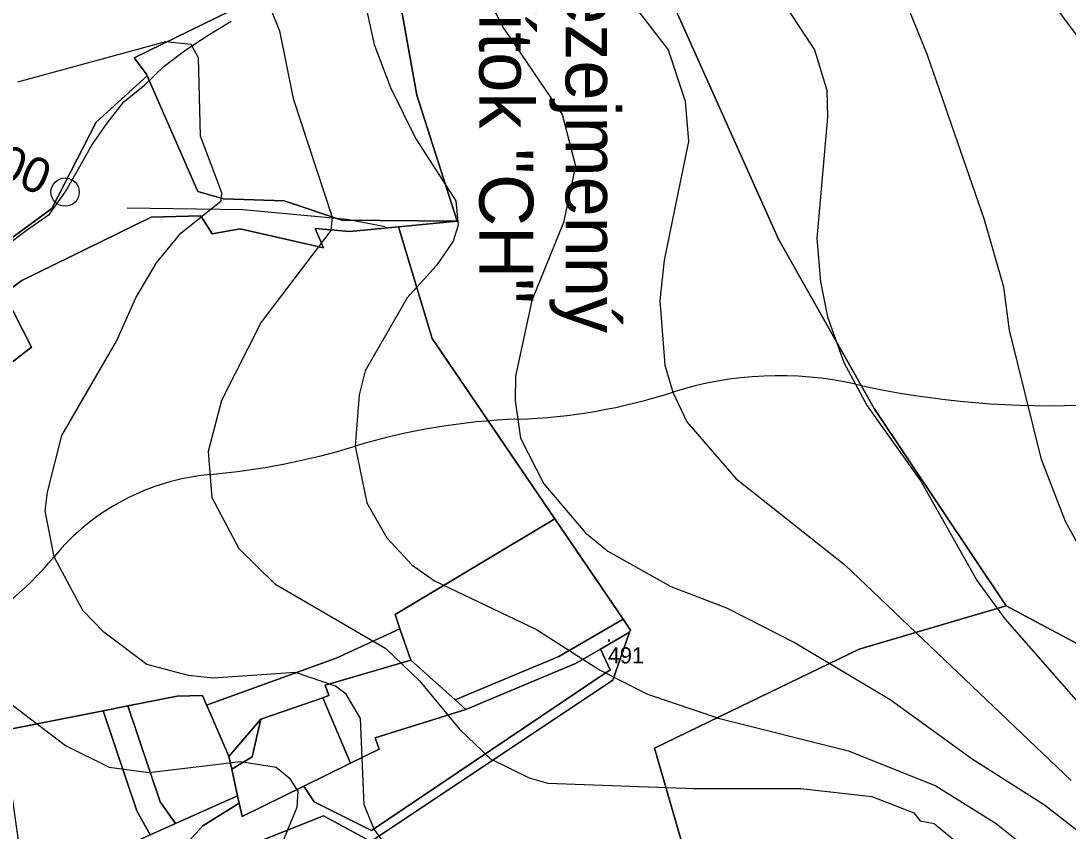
# Model space of a CAD drawing. Extents: x -510989 to -501240, y -1184665 to -1176089.
# Drawn here: x -509708.8 to -509320.3, y -1177679.8 to -1177379.3 of the extents above; entities that cross this region are included whole.
import ezdxf

# ---------------------------------------------------------------- set-up
doc = ezdxf.new("R2010")
doc.units = 0
for name, color, linetype in [('lesni_pozemek', 7, 'Continuous'), ('NAVRH_rozvodnice', 7, 'Continuous'), ('orna_puda', 7, 'Continuous'), ('ostatni_plocha_x_neplodna_puda', 7, 'Continuous'), ('ostatni_plocha_x_ostatni_komunikace', 7, 'Continuous'), ('STAV_vyrazne_udolnice', 7, 'Continuous'), ('trasovani_toku', 7, 'Continuous'), ('trvaly_travni_porost', 7, 'Continuous'), ('vrstevnice_01', 7, 'Continuous'), ('vrstevnice_02', 7, 'Continuous'), ('vrstevnice_05', 7, 'Continuous'), ('zahrada', 7, 'Continuous'), ('zastavena_plocha_a_nadvori', 7, 'Continuous')]:
    doc.layers.add(name, color=color, linetype=linetype)

msp = doc.modelspace()

# ---------------------------------------------------------------- linework, layer by layer
at = {"layer": 'lesni_pozemek'}
for points in [[(-509307.58, -1177615.25), (-509343.27, -1177596.17), (-509392.19, -1177523.08), (-509427.76, -1177460.22), (-509483.45, -1177336)], [(-509483.45, -1177336), (-509427.76, -1177460.22), (-509392.19, -1177523.08), (-509343.27, -1177596.17), (-509397.8, -1177612.27), (-509449.55, -1177637.32), (-509473.73, -1177649.02), (-509463.07, -1177685.78)], [(-509668.22, -1177702.68), (-509596.6, -1177674.14), (-509578.99, -1177683.68), (-509489.24, -1177623.79), (-509482.96, -1177605.95), (-509482.69, -1177605.19), (-509485.42, -1177601.19), (-509510.77, -1177563.96), (-509556.29, -1177497.11), (-509568.76, -1177455.65), (-509546.91, -1177453.53), (-509561.97, -1177406.86), (-509572.95, -1177345.3)], [(-509631, -1177375.54), (-509666.85, -1177393), (-509662.19, -1177399.04), (-509661.92, -1177399.66), (-509680.94, -1177416.84), (-509697.38, -1177448.86), (-509762.27, -1177496.39), (-509774.65, -1177504.38), (-509790.33, -1177514.5), (-509803.69, -1177521.05), (-509822.77, -1177518.7), (-509793.37, -1177502.17), (-509802.43, -1177486.07), (-509850.77, -1177515.75), (-509864.33, -1177527.68), (-509871.08, -1177519.58), (-509909.37, -1177546.26), (-509910.59, -1177544.53), (-509920.45, -1177530.57), (-509905.31, -1177521.45), (-509903.04, -1177450.59), (-509835.36, -1177418.23), (-509751.69, -1177352.23)]]:
    msp.add_lwpolyline(points, dxfattribs=at)
msp.add_lwpolyline([(-509397.8, -1177612.27), (-509343.27, -1177596.17), (-509307.58, -1177615.25), (-509273.09, -1177665), (-509315.44, -1177685.24), (-509336.68, -1177703.21), (-509377.83, -1177696.33), (-509381.06, -1177712.35), (-509395.4, -1177703.59), (-509428.68, -1177701.8), (-509460.46, -1177711.83), (-509462.62, -1177705), (-509463.07, -1177685.78), (-509473.73, -1177649.02), (-509449.55, -1177637.32)], close=True, dxfattribs=at)
at = {"layer": 'NAVRH_rozvodnice'}
for centre, radius, start, end in [((-509327.54, -1177195.98), 325.99, 257.3092, 319.4646), ((-509427.52, -1177639.96), 129.11, 77.3092, 107.7616), ((-509531.7, -1177314.74), 212.38, 271.9542, 287.7616), ((-509516.41, -1177762.7), 235.84, 91.9542, 106.8599), ((-509663.19, -1177278.37), 270.25, 275.2094, 286.8599), ((-509630.93, -1177632.26), 85.11, 95.2094, 140.3942), ((-509791.78, -1177499.16), 123.67, 297.3565, 320.3942)]:
    msp.add_arc(centre, radius, start, end, dxfattribs=at)
at = {"layer": 'orna_puda'}
for points in [[(-509570.02, -1177599.49), (-509510.77, -1177563.96), (-509485.42, -1177601.19), (-509509.18, -1177614.97), (-509547.74, -1177631.1), (-509564.19, -1177616.36), (-509568.18, -1177604.8)], [(-509719.86, -1177643.27), (-509678.3, -1177635.13), (-509665.79, -1177672.22), (-509660.81, -1177681.17), (-509707.03, -1177702.63), (-509708.88, -1177689.34), (-509711.8, -1177668.29), (-509713.07, -1177664.37)]]:
    msp.add_lwpolyline(points, close=True, dxfattribs=at)
at = {"layer": 'ostatni_plocha_x_neplodna_puda'}
for points in [[(-509493.75, -1177612.24), (-509482.96, -1177605.95), (-509489.24, -1177623.79), (-509578.99, -1177683.68), (-509596.6, -1177674.14), (-509668.22, -1177702.68), (-509677.09, -1177705.72), (-509669.63, -1177698.49), (-509651.95, -1177689.42), (-509641.31, -1177677.76), (-509627.8, -1177669.37), (-509626.7, -1177674.34), (-509603.8, -1177663.1), (-509599.97, -1177668.97), (-509578.73, -1177679.51), (-509490.25, -1177619.92)], [(-509631.64, -1177652.13), (-509619.84, -1177638.21), (-509623.01, -1177652.18), (-509630.61, -1177656.76)]]:
    msp.add_lwpolyline(points, close=True, dxfattribs=at)
at = {"layer": 'ostatni_plocha_x_ostatni_komunikace'}
for points in [[(-509482.69, -1177605.19), (-509482.96, -1177605.95), (-509493.75, -1177612.24), (-509503.04, -1177617.66), (-509543.7, -1177634.72), (-509547.74, -1177631.1), (-509509.18, -1177614.97), (-509485.42, -1177601.19)], [(-509628.4, -1177666.69), (-509627.8, -1177669.37), (-509641.31, -1177677.76), (-509651.95, -1177689.42), (-509669.63, -1177698.49), (-509677.09, -1177705.72), (-509678.31, -1177706.14), (-509689.95, -1177715.27), (-509704.37, -1177721.75), (-509707.03, -1177702.63), (-509660.81, -1177681.17), (-509651.5, -1177677.01)]]:
    msp.add_lwpolyline(points, close=True, dxfattribs=at)
at = {"layer": 'STAV_vyrazne_udolnice'}
msp.add_lwpolyline([(-509669.37, -1177448.54), (-509626.47, -1177449.24), (-509587.78, -1177452.75), (-509573.72, -1177455.57)], dxfattribs=at)
at = {"layer": 'trasovani_toku'}
for p, q in [((-509639.3, -1177384.58), (-509630.8, -1177379.32)), ((-509647.68, -1177390.04), (-509639.3, -1177384.58)), ((-509655.63, -1177396.11), (-509647.68, -1177390.04)), ((-509662.86, -1177403.02), (-509655.63, -1177396.11)), ((-509670.67, -1177409.27), (-509662.86, -1177403.02)), ((-509676.83, -1177417.14), (-509670.67, -1177409.27)), ((-509682.46, -1177425.41), (-509676.83, -1177417.14)), ((-509687.42, -1177434.09), (-509682.46, -1177425.41)), ((-509692.41, -1177442.76), (-509687.42, -1177434.09)), ((-509698.15, -1177450.94), (-509692.41, -1177442.76)), ((-509706.4, -1177456.59), (-509698.15, -1177450.94)), ((-509714.35, -1177462.66), (-509706.4, -1177456.59))]:
    msp.add_line(p, q, dxfattribs=at)
msp.add_circle((-509692.41, -1177442.76), 5.25, dxfattribs=at)
at = {"layer": 'trvaly_travni_porost'}
for points in [[(-509572.95, -1177345.3), (-509561.97, -1177406.86), (-509546.91, -1177453.53), (-509589.76, -1177453.23), (-509611.17, -1177445.97), (-509633.68, -1177445.21), (-509643.12, -1177442.55), (-509661.92, -1177399.66), (-509662.19, -1177399.04), (-509666.85, -1177393), (-509631, -1177375.54), (-509588.68, -1177354.29)], [(-509661.92, -1177399.66), (-509643.12, -1177442.55), (-509633.68, -1177445.21), (-509611.17, -1177445.97), (-509589.76, -1177453.23), (-509546.91, -1177453.53), (-509568.76, -1177455.65), (-509586.79, -1177457.4), (-509599.68, -1177456.28), (-509596.6, -1177463.39), (-509627.43, -1177456.33), (-509637.9, -1177458.29), (-509642.03, -1177451.61), (-509660.52, -1177452), (-509708.48, -1177475.5), (-509715.05, -1177480.43), (-509704.91, -1177500.28), (-509737.25, -1177525.22), (-509754.82, -1177531.88), (-509774.65, -1177504.38), (-509762.27, -1177496.39), (-509697.38, -1177448.86), (-509680.94, -1177416.84)], [(-509568.18, -1177604.8), (-509564.19, -1177616.36), (-509585.32, -1177622.55), (-509595.98, -1177625.67), (-509594.6, -1177629.53), (-509596.8, -1177630.29), (-509619.84, -1177638.21), (-509631.64, -1177652.13), (-509632.2, -1177650.84), (-509639.71, -1177633.49), (-509639.91, -1177633.04), (-509591.84, -1177615.63)], [(-509503.04, -1177617.66), (-509493.75, -1177612.24), (-509490.25, -1177619.92), (-509578.73, -1177679.51), (-509599.97, -1177668.97), (-509603.8, -1177663.1), (-509586.55, -1177654.63), (-509575.89, -1177649.39), (-509577.38, -1177645.15), (-509543.7, -1177634.72)]]:
    msp.add_lwpolyline(points, close=True, dxfattribs=at)
msp.add_lwpolyline([(-509737.25, -1177525.22), (-509704.91, -1177500.28), (-509715.05, -1177480.43), (-509708.48, -1177475.5), (-509660.52, -1177452), (-509642.03, -1177451.61), (-509637.9, -1177458.29), (-509627.43, -1177456.33), (-509596.6, -1177463.39), (-509599.68, -1177456.28), (-509586.79, -1177457.4), (-509568.76, -1177455.65), (-509556.29, -1177497.11), (-509510.77, -1177563.96), (-509570.02, -1177599.49), (-509568.18, -1177604.8), (-509591.84, -1177615.63), (-509639.91, -1177633.04), (-509641.48, -1177629.44), (-509650.79, -1177629.74), (-509669.12, -1177633.33), (-509678.3, -1177635.13), (-509719.86, -1177643.27)], dxfattribs=at)
at = {"layer": 'vrstevnice_01'}
for points in [[(-509584.59, -1177357), (-509577.81, -1177388), (-509571.69, -1177404), (-509562.31, -1177423), (-509547.41, -1177446), (-509546.59, -1177455), (-509548.41, -1177461), (-509554.59, -1177470), (-509565.5, -1177482), (-509581.09, -1177509), (-509583.31, -1177518), (-509584.81, -1177537), (-509580.5, -1177558), (-509573.09, -1177571), (-509563.81, -1177581), (-509555.31, -1177587), (-509517.5, -1177605), (-509494.09, -1177620), (-509476.31, -1177629), (-509449.59, -1177638), (-509401.81, -1177650), (-509369.31, -1177663), (-509347, -1177677), (-509275.91, -1177734)], [(-509492.5, -1177359), (-509468.69, -1177390), (-509462.31, -1177409), (-509461.19, -1177424), (-509470.19, -1177468), (-509471.81, -1177483), (-509469.91, -1177507), (-509466.91, -1177517), (-509461.69, -1177528), (-509443.59, -1177549), (-509403.19, -1177581), (-509319.19, -1177661)], [(-509299.09, -1177605), (-509321.31, -1177565), (-509330.19, -1177542), (-509342.09, -1177494), (-509344.19, -1177478), (-509351.31, -1177453), (-509372.41, -1177392), (-509381.69, -1177369)], [(-509574.19, -1177684), (-509577.81, -1177679), (-509581.5, -1177670), (-509582.81, -1177638), (-509588.19, -1177629), (-509592.09, -1177626), (-509606.91, -1177621), (-509637.5, -1177623), (-509646.59, -1177622), (-509662.09, -1177618), (-509678.09, -1177606), (-509685.81, -1177598), (-509696.5, -1177578), (-509699.81, -1177561), (-509698.91, -1177554), (-509693.69, -1177533), (-509673.31, -1177498), (-509666.19, -1177482), (-509658.5, -1177469), (-509649.5, -1177458), (-509634.5, -1177446), (-509634.31, -1177443), (-509642.19, -1177422), (-509642.91, -1177393), (-509645.69, -1177388), (-509655.19, -1177387), (-509710.09, -1177402)]]:
    msp.add_lwpolyline(points, dxfattribs=at)
at = {"layer": 'vrstevnice_02'}
for points in [[(-509542.81, -1177357), (-509529.81, -1177382), (-509508, -1177414), (-509503, -1177433), (-509507.5, -1177454), (-509519.31, -1177483), (-509525.31, -1177511), (-509525.5, -1177520), (-509523.41, -1177534), (-509514.81, -1177551), (-509499.5, -1177569), (-509491, -1177576), (-509467.69, -1177589), (-509447, -1177597), (-509421.59, -1177610), (-509386.31, -1177631), (-509355.91, -1177653), (-509329.09, -1177670), (-509269.91, -1177716)], [(-509428.81, -1177368), (-509414.41, -1177390), (-509409.81, -1177405), (-509409.5, -1177415), (-509413.5, -1177460), (-509412.19, -1177476), (-509409.5, -1177489), (-509403.5, -1177506), (-509394.81, -1177522), (-509374.91, -1177550), (-509354, -1177587), (-509343.81, -1177601), (-509314, -1177635)], [(-509616.41, -1177374), (-509612.91, -1177383), (-509607.81, -1177408), (-509593.31, -1177452), (-509593.81, -1177457), (-509619.69, -1177491), (-509634.41, -1177520), (-509639.31, -1177539), (-509638, -1177556), (-509628, -1177575), (-509614.59, -1177588), (-509573.41, -1177612), (-509560.91, -1177624), (-509546.09, -1177642), (-509534.59, -1177653), (-509520.19, -1177660), (-509513.31, -1177662), (-509459.09, -1177664), (-509419.41, -1177664), (-509393.09, -1177667), (-509377.59, -1177673), (-509375.19, -1177676), (-509370, -1177677), (-509298.59, -1177736)], [(-509325.81, -1177373), (-509312.41, -1177391)], [(-509720, -1177627), (-509692.31, -1177648), (-509676.09, -1177656), (-509661.41, -1177658), (-509627.31, -1177654), (-509614.09, -1177656), (-509609.31, -1177660), (-509606.09, -1177665), (-509606.41, -1177671), (-509614.69, -1177691)]]:
    msp.add_lwpolyline(points, dxfattribs=at)
at = {"layer": 'zahrada'}
for points in [[(-509619.84, -1177638.21), (-509596.8, -1177630.29), (-509586.55, -1177654.63), (-509603.8, -1177663.1), (-509626.7, -1177674.34), (-509627.8, -1177669.37), (-509628.4, -1177666.69), (-509630.61, -1177656.76), (-509623.01, -1177652.18)], [(-509678.3, -1177635.13), (-509669.12, -1177633.33), (-509657.13, -1177668.92), (-509651.5, -1177677.01), (-509660.81, -1177681.17), (-509665.79, -1177672.22)]]:
    msp.add_lwpolyline(points, close=True, dxfattribs=at)
at = {"layer": 'zastavena_plocha_a_nadvori'}
for points in [[(-509585.32, -1177622.55), (-509564.19, -1177616.36), (-509547.74, -1177631.1), (-509543.7, -1177634.72), (-509577.38, -1177645.15), (-509575.89, -1177649.39), (-509586.55, -1177654.63), (-509596.8, -1177630.29), (-509594.6, -1177629.53), (-509595.98, -1177625.67)], [(-509650.79, -1177629.74), (-509641.48, -1177629.44), (-509639.91, -1177633.04), (-509639.71, -1177633.49), (-509632.2, -1177650.84), (-509631.64, -1177652.13), (-509630.61, -1177656.76), (-509628.4, -1177666.69), (-509651.5, -1177677.01), (-509657.13, -1177668.92), (-509669.12, -1177633.33)]]:
    msp.add_lwpolyline(points, close=True, dxfattribs=at)

# ---------------------------------------------------------------- texts
at = {"layer": 'NAVRH_rozvodnice'}
for s, p in [('Bezejmenný', (-509506.73, -1177347.83)), ('přítok "CH"', (-509538.73, -1177352.24))]:
    msp.add_text(s, height=20, rotation=270, dxfattribs=at).set_placement(p)
at = {"layer": 'trasovani_toku'}
msp.add_text('0,500', height=13, rotation=336.6357, dxfattribs=at).set_placement((-509741.37, -1177426.96))
at = {"layer": 'vrstevnice_05'}
for s, p in [('.', (-509491.7, -1177609.54)), ('491', (-509491.03, -1177617.59))]:
    msp.add_text(s, height=6, dxfattribs=at).set_placement(p)

doc.saveas('drawing.dxf')
